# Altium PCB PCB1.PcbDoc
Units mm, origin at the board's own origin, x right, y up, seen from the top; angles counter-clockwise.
Board outline 50 x 45 mm, 2 copper layers (Top Layer, Bottom Layer); 31 components, 19 nets, 91 pads, 18 vias.
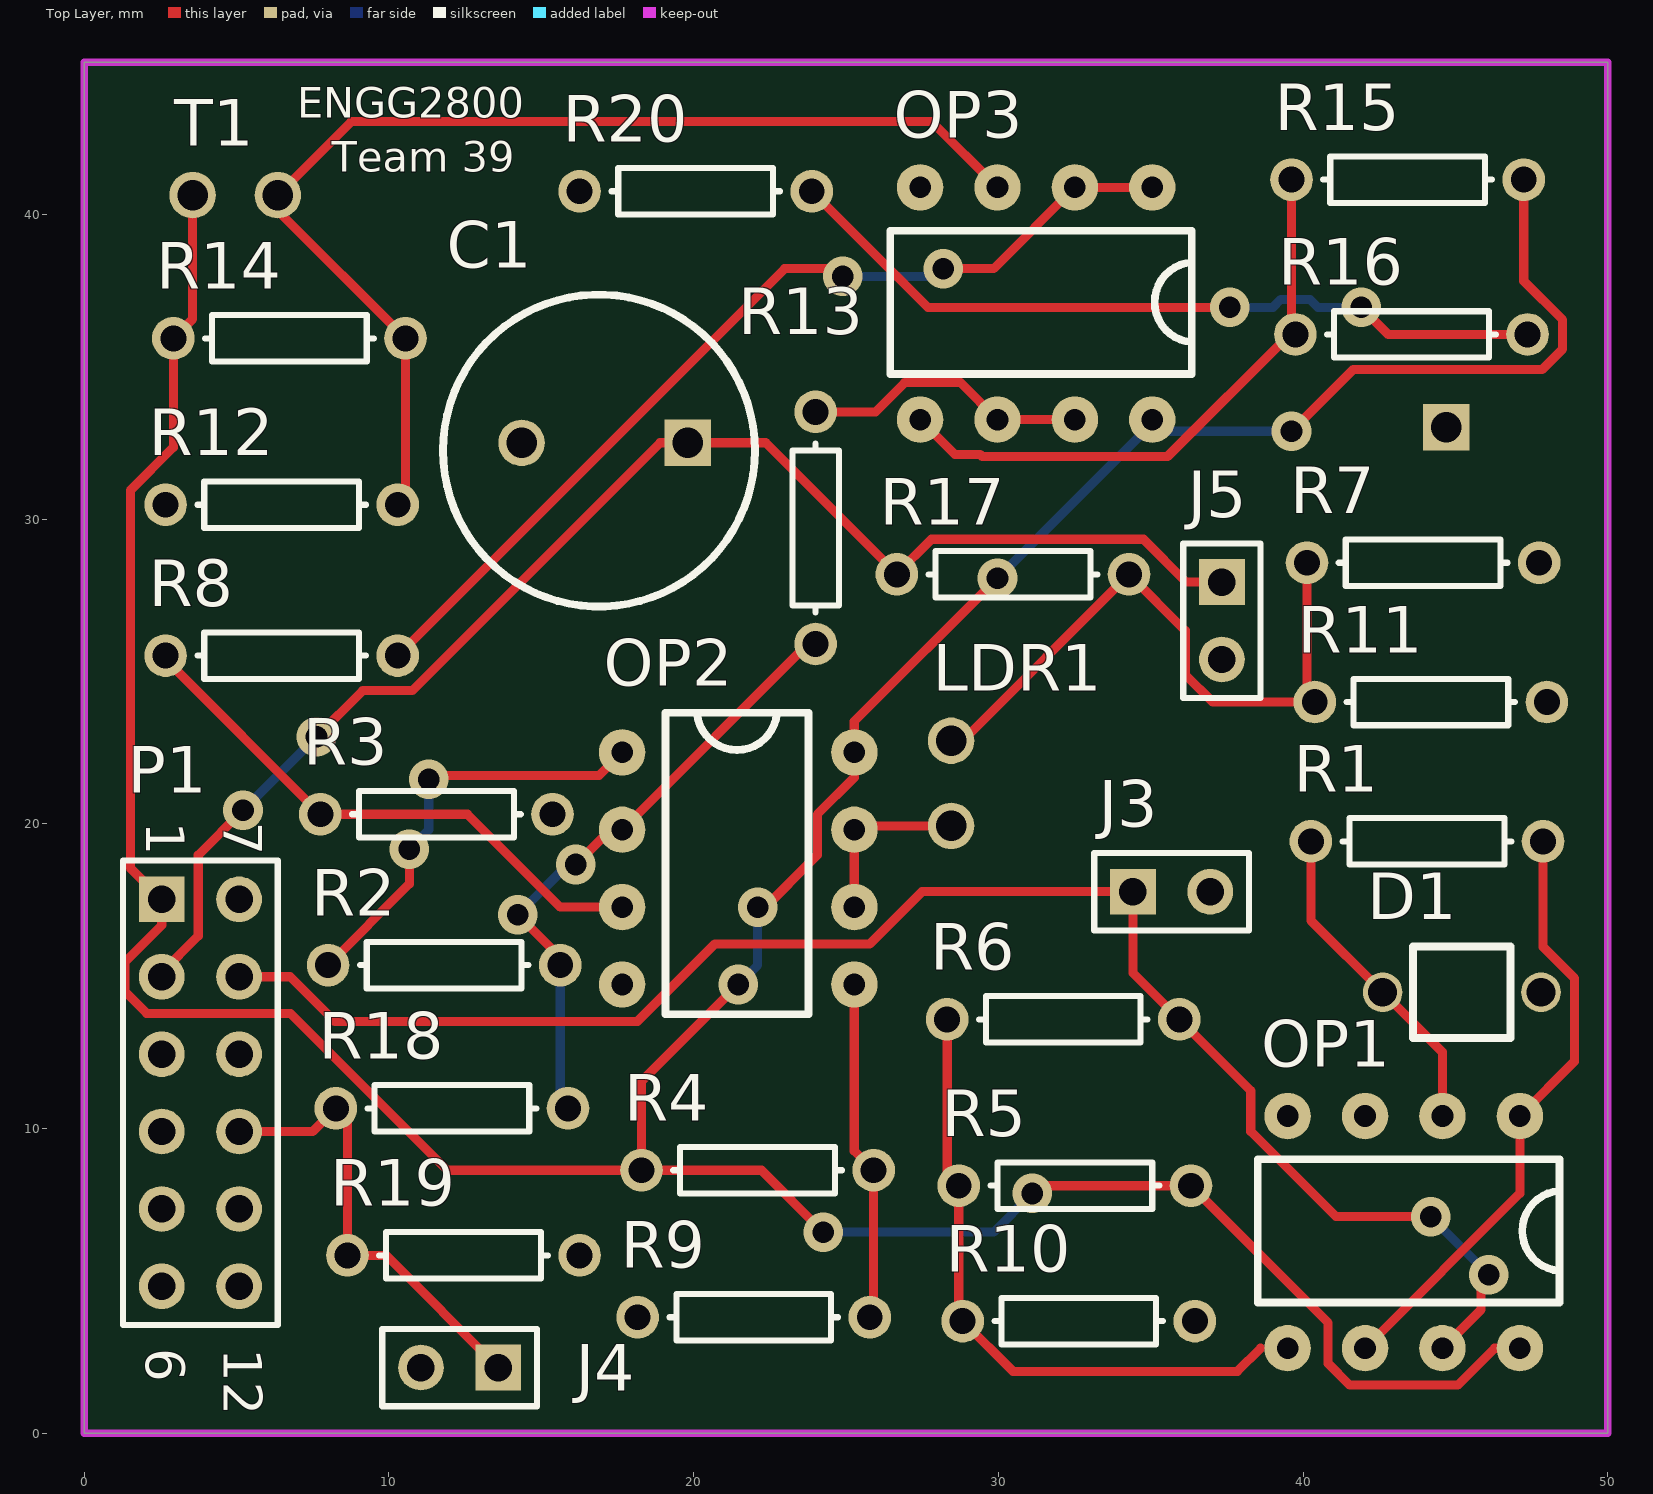
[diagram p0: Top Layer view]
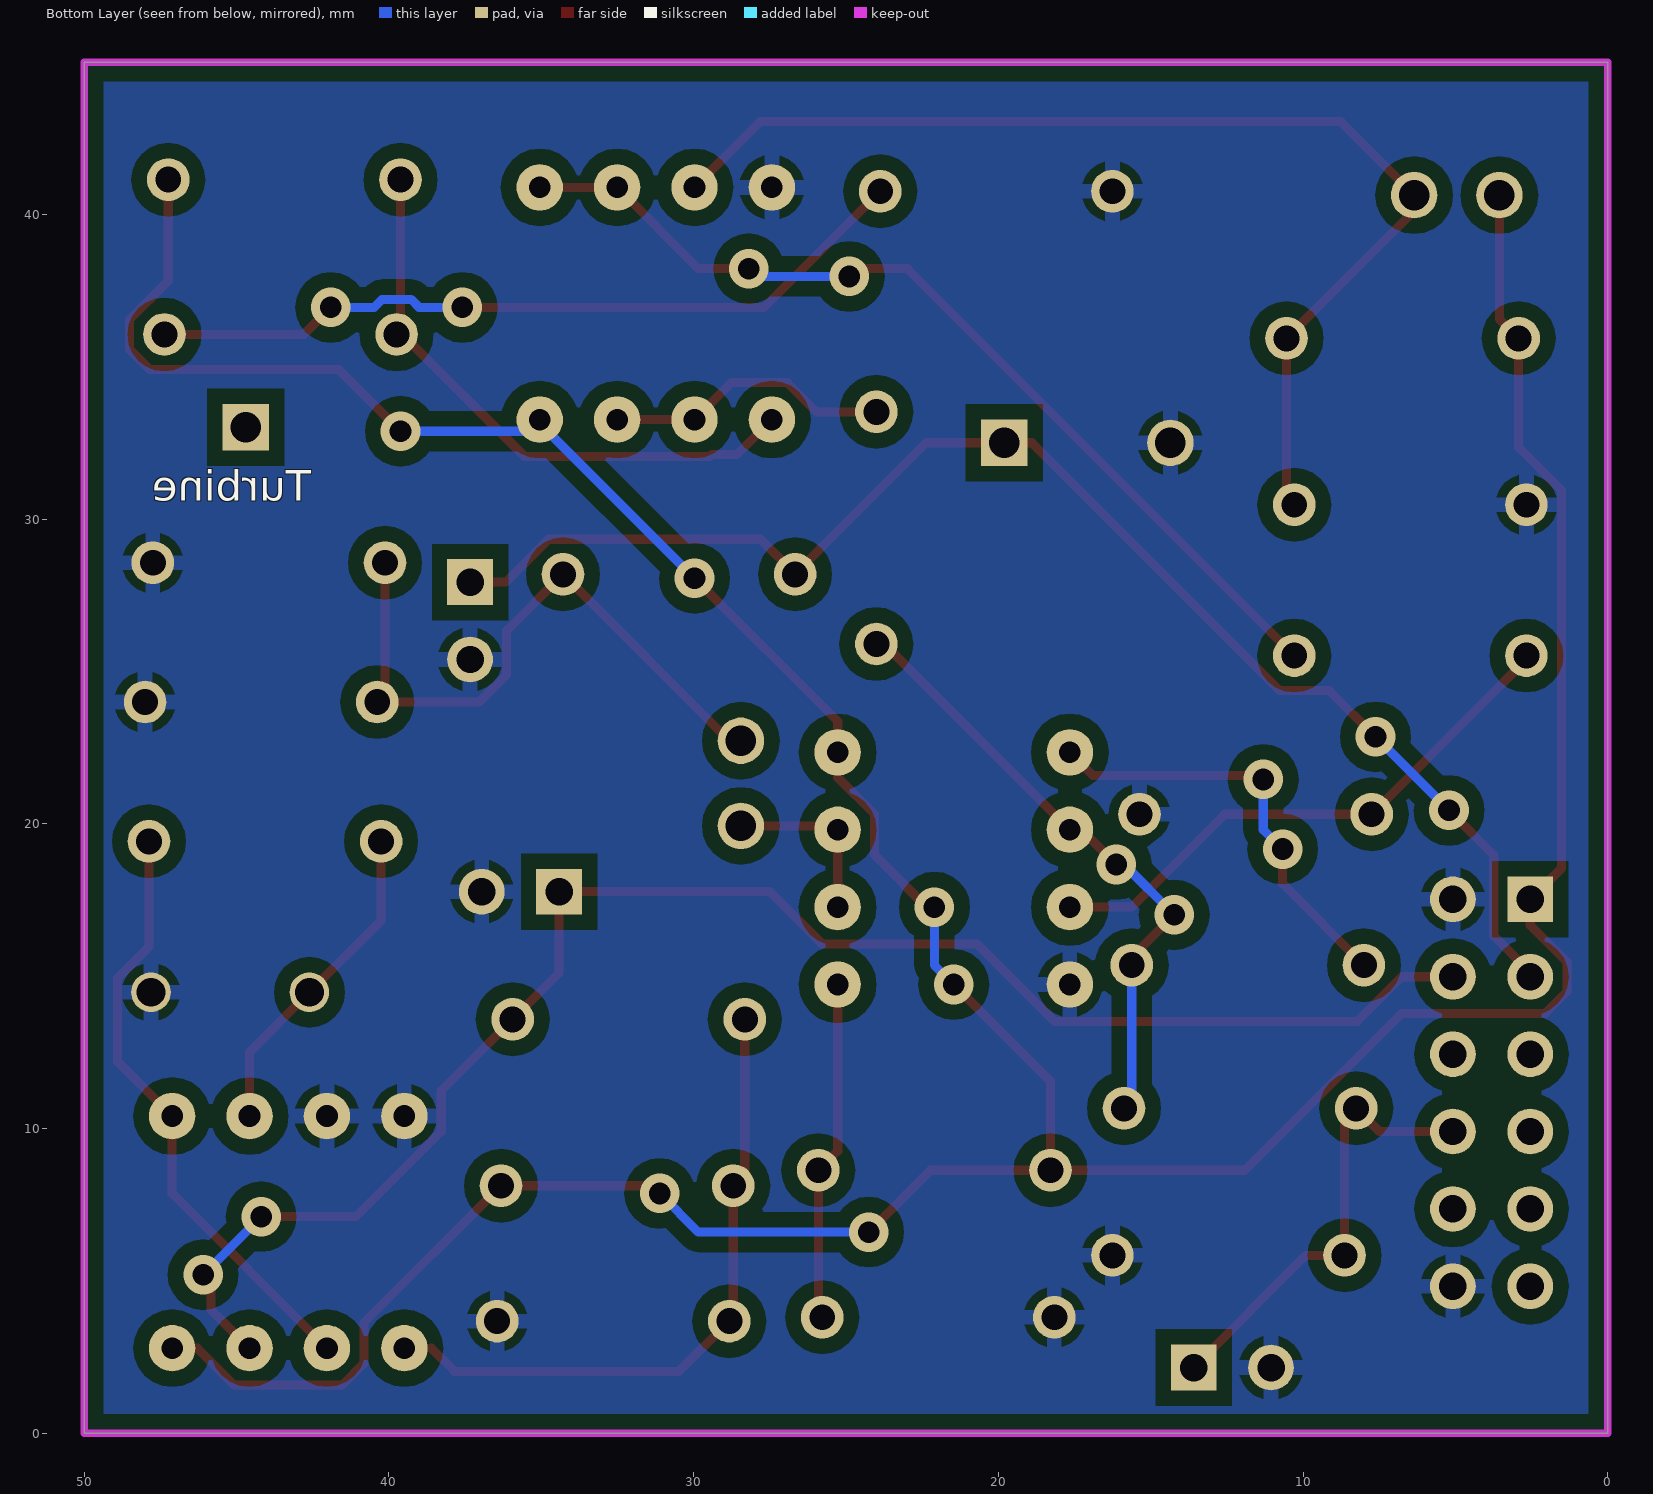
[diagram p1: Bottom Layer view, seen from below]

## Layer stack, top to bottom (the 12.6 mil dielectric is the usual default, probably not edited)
Top Layer: signal copper 0.0356
Dielectric: dielectric 0.32, FR-4, Dk 4.8
Bottom Layer: signal copper 0.0356

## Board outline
0,0 0,45 50,45 50,0

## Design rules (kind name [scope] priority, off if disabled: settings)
Clearance [All] p1: gap=0.3
ComponentClearance [All] p1: gap=0.3 collisioncheckmode=3 verticalgap=0.3 showdistances=FALSE
HoleSize [All] p1: absolutevalues=TRUE maxlimit=0.7 minlimit=0.7 maxpercent=80.000 minpercent=20.000
HoleToHoleClearance [All] p1: gap=0.15 allowstackedmicrovias=TRUE
MinimumSolderMaskSliver [All] p1: minsoldermaskwidth=0.01
PolygonConnect [All] p1: connectstyle=Relief reliefconductorwidth=0.5 reliefentries=4 polygonreliefangle="90 Angle" airgapwidth=0.3
RoutingVias [All] p1: holewidth=0.7 width=1.3 viastyle="Through Hole" minholewidth=0.7 minwidth=1.3 maxholewidth=1.5 maxwidth=3
SilkToSilkClearance [All] p1: silktosilkclearance=0.01
SilkToSolderMaskClearance [IsPad] p1: minsilkscreentomaskgap=0.01 clearancetoexposedcopper=TRUE
SolderMaskExpansion [All] p1: expansion=0.102
Width [All] p1: maxlimit=2 minlimit=0.3 preferedwidth=0.5
22 further rules are at their usual default settings.

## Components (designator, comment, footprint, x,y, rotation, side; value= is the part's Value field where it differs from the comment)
C1 "Cap Pol1" PCBComponent_1#1 19.812,32.512 r0 top
D1 "BPW34" BPW34 45.212,14.478 r0 top
J3 "Wind Speed Test Point" HDR1X2 34.417,17.78 r0 top
J4 "Thermistor Test Point" HDR1X2 13.589,2.159 r180 top
J5 "LDR Test Point" HDR1X2 37.338,27.94 r270 top
LDR1 "LDR" PCBComponent_1#2 28.448,19.939 r90 top
OP1 "LM358" LM358 43.307,6.604 r180 top
OP2 "LM358" LM358 21.463,18.542 r270 top
OP3 "LM358" LM358 31.242,37.084 r180 top
P1 "Header 6X2A" HDR2X6_CEN 2.54,17.526 r270 top
R1 "Res1" AXIAL-0.3 44.069,19.431 r0 top
R2 "Res1" AXIAL-0.3 11.811,15.367 r180 top
R3 "Res1" AXIAL-0.3 11.557,20.32 r180 top
R4 "Res1" AXIAL-0.3 22.098,8.636 r180 top
R5 "Res1" AXIAL-0.3 32.512,8.128 r0 top
R6 "Res1" AXIAL-0.3 32.131,13.589 r180 top
R7 "Res1" AXIAL-0.3 43.942,28.575 r0 top
R8 "Res1" AXIAL-0.3 6.477,25.527 r180 top
R9 "Res1" AXIAL-0.3 21.971,3.81 r0 top
R10 "Res1" AXIAL-0.3 32.639,3.683 r180 top
R11 "Res1" AXIAL-0.3 44.196,24.003 r0 top
R12 "Res1" AXIAL-0.3 6.477,30.48 r0 top
R13 "Res1" AXIAL-0.3 24.003,29.718 r90 top
R14 "Res1" AXIAL-0.3 6.731,35.941 r180 top
R15 "Res1" AXIAL-0.3 43.434,41.148 r0 top
R16 "Res1" AXIAL-0.3 43.561,36.068 r180 top
R17 "Res1" AXIAL-0.3 30.48,28.194 r180 top
R18 "Res1" AXIAL-0.3 12.065,10.668 r0 top
R19 "Res1" AXIAL-0.3 12.446,5.842 r180 top
R20 "Res1" AXIAL-0.3 20.066,40.767 r0 top
T1 "Thermistor" PCBComponent_1#2 6.35,40.64 r180 top

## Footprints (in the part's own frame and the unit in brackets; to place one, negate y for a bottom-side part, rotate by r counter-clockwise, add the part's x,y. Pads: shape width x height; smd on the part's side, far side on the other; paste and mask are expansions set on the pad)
AXIAL-0.3 [mm] "Axial Device, Thru-Hole; 2 Leads; 0.3 in Pin Spacing"
  round 1.4 hole 0.85: 1(-3.81,0) 2(3.81,0)
  silkscreen extent -2.77,-0.76 2.77,0.76
BPW34 [mm]
  round 1.3 hole 0.95: 1(-2.6,0) 2(2.6,0)
  silkscreen extent -1.6,-1.5 1.6,1.5
HDR1X2 [mm] "Connector; Header; 2 Position"
  rect 1.5x1.5 hole 0.9: 1(0,0)
  round 1.5 hole 0.9: 2(2.54,0)
  silkscreen extent -1.27,-1.27 3.81,1.27
HDR2X6_CEN [mm] "Connector; Header; 6x2 Position"
  rect 1.5x1.5 hole 0.9: 1(0,0)
  round 1.5 hole 0.9: 2(2.54,0) 3(5.08,0) 4(7.62,0) 5(10.16,0) 6(12.7,0) 7(0,2.54) 8(2.54,2.54) 9(5.08,2.54) 10(7.62,2.54) 11(10.16,2.54) 12(12.7,2.54)
  silkscreen extent -1.27,-1.27 13.97,3.81
LM358 [mil]
  round 60 hole 27.95: 1(-150,-150) 2(-50,-150) 3(50,-150) 4(150,-150) 5(150,150) 6(50,150) 7(-50,150) 8(-150,150)
  silkscreen extent -201,-94 189,91
PCBComponent_1#1 [mil]
  rect 60x60 hole 39.37: 1(0,0)
  round 60 hole 39.37: 2(-215,0)
  silkscreen extent -317,-211 87,191
PCBComponent_1#2 [mil]
  round 60 hole 39.37: 1(0,0) 2(110,0)

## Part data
C1: "Polarized Capacitor (Radial)"
J3 J4 J5: library part "Header 2", "Header, 2-Pin"
P1: "Header, 6-Pin, Dual row"
R1 R2 R3 R4 R5 R6 R7 R8 R9 R10 R11 R12 R13 R14 R15 R16 R17 R18 R19 R20: "Resistor"

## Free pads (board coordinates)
  rect 1.524x1.524 hole 1: 2(44.704,33.02)

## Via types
v1: diameter 1.3, hole 0.711, Top Layer to Bottom Layer, 18 vias

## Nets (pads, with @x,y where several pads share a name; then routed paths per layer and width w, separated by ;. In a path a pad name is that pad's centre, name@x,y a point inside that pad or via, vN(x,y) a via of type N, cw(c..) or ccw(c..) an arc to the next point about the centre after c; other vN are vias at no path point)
+5V: OP1.8 OP2.8 OP3.8 P1.1 R4.2 R5.2 R14.2 R15.2 T1.2 | length 134.1
  Top Layer w0.3: T1.2 3.556,36.576 R14.2 2.921,32.36 1.517,30.956 1.517,18.549 P1.1 2.54,16.683 1.34,15.483 1.34,14.489 2.043,13.786 6.763,13.786 11.913,8.636 R4.2 ; v1(21.463,14.732) 18.288,11.557 R4.2 ; v1(22.098,17.272) 22.225,17.145 24.061,18.981 24.061,20.314 25.273,21.526 OP2.8 25.273,23.368 v1(29.972,28.067) ; v1(24.257,6.604) 22.225,8.636 R4.2 ; v1(31.115,7.874) 31.369,8.128 R5.2 40.825,3.625 40.825,2.292 41.535,1.582 45.079,1.582 46.291,2.794 OP1.8 ; v1(39.624,32.893) 41.649,34.918 47.847,34.918 48.521,35.592 48.521,36.544 47.244,37.821 R15.2
  Bottom Layer w0.3: v1(21.463,14.732) 22.098,15.367 v1(22.098,17.272) ; v1(24.257,6.604) 29.845,6.604 v1(31.115,7.874) ; v1(29.972,28.067) OP3.8@35.052,33.147 ; OP3.8 35.433,32.893 v1(39.624,32.893)
FILTER: LDR1.2 R7.1 R11.1 R17.1 | length 21.1
  Top Layer w0.3: LDR1.2 28.829,22.733 R17.1 36.138,26.346 36.138,24.903 37.038,24.003 R11.1 ; R11.1@40.132,24.257 R7.1
GND: C1.2 D1.2 J3.2 J4.2 J5.2 OP1.3 OP1.4 OP2.4 OP3.4 P1.7 P1.12 R3.1 R7.2 R9.1 R10.1 R11.2 R12.1 R19.1 R20.1
INVERTING1: OP2.2 R2.1 R13.1 R18.2 | length 19.8
  Top Layer w0.3: v1(14.224,17.018) 15.621,15.621 R2.1 ; v1(16.129,18.669) OP2.2@17.272,19.812 ; OP2.2 23.749,25.908 R13.1
  Bottom Layer w0.3: v1(14.224,17.018) 15.875,18.669 v1(16.129,18.669) ; R18.2@15.621,10.922 R2.1
LDR: C1.1 J5.1 P1.2 R17.2 | length 46.4
  Top Layer w0.3: P1.2@2.54,15.126 3.74,16.326 3.74,18.98 v1(5.207,20.447) ; v1(7.62,22.86) 9.137,24.377 10.763,24.377 18.898,32.512 C1.1 22.366,32.512 26.67,28.208 27.806,29.344 34.766,29.344 36.17,27.94 J5.1
  Bottom Layer w0.3: v1(5.207,20.447) v1(7.62,22.86)
NetD1_1: D1.1 OP1.2 R1.1 | length 10.8
  Top Layer w0.3: R1.1 40.259,16.831 D1.1 44.577,12.513 OP1.2
NetLDR1_1: LDR1.1 OP2.6 OP2.7 | length 5.8
  Top Layer w0.3: OP2.6 OP2.7 25.4,19.939 LDR1.1
NetOP1_1: OP1.1 OP1.6 R1.2 | length 19.9
  Top Layer w0.3: OP1.6 47.117,7.874 OP1.1 48.912,12.209 48.912,14.934 47.879,15.967 R1.2
NetOP1_5: OP1.5 R5.1 R6.2 R10.2 | length 20.2
  Top Layer w0.3: R5.1@28.321,8.509 R6.2 ; R10.2@28.702,3.81 R5.1 ; R10.2 30.48,2.032 37.846,2.032 38.608,2.794
NetOP2_1: OP2.1 R2.2 | length 14.4
  Top Layer w0.3: R2.2 10.668,18.034 v1(10.668,19.177) ; v1(11.303,21.463) 11.303,21.336 11.557,21.59 16.891,21.59 OP2.1
  Bottom Layer w0.3: v1(10.668,19.177) 11.303,19.812 v1(11.303,21.463)
NetOP2_3: OP2.3 R3.2 R8.2 | length 18.5
  Top Layer w0.3: R8.2 2.667,25.4 R3.2 12.573,20.32 15.621,17.272 OP2.3
NetOP3_1: OP3.1 OP3.2 R8.1 | length 31.5
  Top Layer w0.3: R8.1 22.987,38.227 24.892,38.227 v1(24.892,37.973) ; v1(28.194,38.227) 29.845,38.227 OP3.2 OP3.1
  Bottom Layer w0.3: v1(24.892,37.973) 27.94,37.973 v1(28.194,38.227)
NetOP3_3: OP3.3 R12.2 R14.1 T1.1 | length 37.2
  Top Layer w0.3: R12.2@10.541,30.734 R14.1 6.35,40.132 T1.1 8.763,43.053 27.813,43.053 OP3.3
NetOP3_5: OP3.5 R15.1 R16.2 | length 19.6
  Top Layer w0.3: OP3.5 28.575,32.131 29.401,32.131 29.47,32.062 35.554,32.062 39.56,36.068 R16.2 39.624,36.195 R15.1
NetOP3_6: OP3.6 OP3.7 R13.2 | length 9.4
  Top Layer w0.3: R13.2 25.972,33.528 26.93,34.486 28.76,34.486 OP3.6 OP3.7
NetR16_1: R16.1 R20.2 | length 25.7
  Top Layer w0.3: R20.2 27.686,36.957 v1(37.592,36.957) ; v1(41.91,36.957) 42.799,36.068 R16.1
  Bottom Layer w0.3: v1(37.592,36.957) 39.014,36.957 39.275,37.218 40.227,37.218 40.488,36.957 v1(41.91,36.957)
NON-INVERTING1: OP2.5 R4.1 R9.2 | length 11.1
  Top Layer w0.3: OP2.5 25.273,9.271 R4.1 R9.2@25.908,3.937
THERMISTOR: J4.1 P1.10 R18.1 R19.2 | length 15
  Top Layer w0.3: P1.10 7.493,9.906 R18.1 8.636,10.287 R19.2 9.906,5.842 J4.1
WIND: J3.1 OP1.7 P1.8 R6.1 | length 54.1
  Top Layer w0.3: P1.8 6.756,14.986 8.222,13.52 18.155,13.52 20.695,16.06 25.775,16.06 27.495,17.78 J3.1 34.417,15.113 R6.1 38.285,11.245 38.285,9.912 41.085,7.112 v1(44.196,7.112) ; OP1.7 45.847,4.064 45.847,5.207 v1(46.101,5.207)
  Bottom Layer w0.3: v1(44.196,7.112) v1(46.101,5.207)
pads on no net: P1.3 P1.4 P1.5 P1.6 P1.9 P1.11

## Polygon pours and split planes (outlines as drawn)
GND on Bottom Layer "GND" (solid, remove dead copper, pour order 8): 0.254,45 50,45 50,0 0.508,0 0,0.508

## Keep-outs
Keep-Out Layer:
  the board outline again, w0.254

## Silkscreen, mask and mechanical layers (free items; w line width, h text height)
Top Overlay:
  text "ENGG2800" at 6.985,43.18 h1
  text "Team 39" at 8.128,41.402 h1
Bottom Overlay:
  text "Turbine" at 42.545,30.607 h1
